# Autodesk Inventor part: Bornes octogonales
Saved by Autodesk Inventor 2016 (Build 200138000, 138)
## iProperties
Created: 2018-03
Part Number: Bornes octogonales
Material: Générique
Document SubType Name: Modeling
Designer: Bruno
Density: 1 g/cm^3
Appearance: Par défaut
Author: Bruno
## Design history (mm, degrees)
feature "Composite1"
body "Srf1"
